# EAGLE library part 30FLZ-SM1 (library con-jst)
CONNECTOR
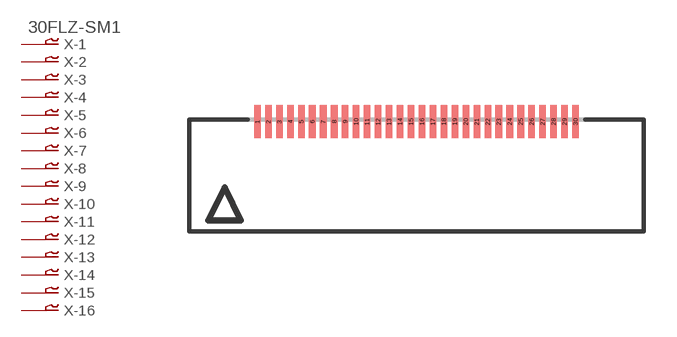
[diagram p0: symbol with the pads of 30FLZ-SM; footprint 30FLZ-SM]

Designator prefix X; gates -1=P-VN -2=P-N -3=P-N -4=P-N -5=P-N -6=P-N -7=P-N -8=P-N -9=P-N -10=P-N -11=P-N -12=P-N -13=P-N -14=P-N -15=P-N -16=P-N -17=P-N -18=P-N -19=P-N -20=P-N -21=P-N -22=P-N -23=P-N -24=P-N -25=P-N -26=P-N -27=P-N -28=P-N -29=P-N -30=P-N

## 30FLZ-SM1 (OC_FARNELL: unknown; OC_NEWARK: unknown)  [30FLZ-SM]
1  -1:1  pas
2  -2:1  pas
3  -3:1  pas
4  -4:1  pas
5  -5:1  pas
6  -6:1  pas
7  -7:1  pas
8  -8:1  pas
9  -9:1  pas
10  -10:1  pas
11  -11:1  pas
12  -12:1  pas
13  -13:1  pas
14  -14:1  pas
15  -15:1  pas
16  -16:1  pas
17  -17:1  pas
18  -18:1  pas
19  -19:1  pas
20  -20:1  pas
21  -21:1  pas
22  -22:1  pas
23  -23:1  pas
24  -24:1  pas
25  -25:1  pas
26  -26:1  pas
27  -27:1  pas
28  -28:1  pas
29  -29:1  pas
30  -30:1  pas

## Footprint 30FLZ-SM (pad centres in mm)
CONNECTOR
smd 0.3 x 1.5: 1 -7.25,2.5; 2 -6.75,2.5; 3 -6.25,2.5; 4 -5.75,2.5; 5 -5.25,2.5; 6 -4.75,2.5; 7 -4.25,2.5; 8 -3.75,2.5; 9 -3.25,2.5; 10 -2.75,2.5; 11 -2.25,2.5; 12 -1.75,2.5; 13 -1.25,2.5; 14 -0.75,2.5; 15 -0.25,2.5; 16 0.25,2.5; 17 0.75,2.5; 18 1.25,2.5; 19 1.75,2.5; 20 2.25,2.5; 21 2.75,2.5; 22 3.25,2.5; 23 3.75,2.5; 24 4.25,2.5; 25 4.75,2.5; 26 5.25,2.5; 27 5.75,2.5; 28 6.25,2.5; 29 6.75,2.5; 30 7.25,2.5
